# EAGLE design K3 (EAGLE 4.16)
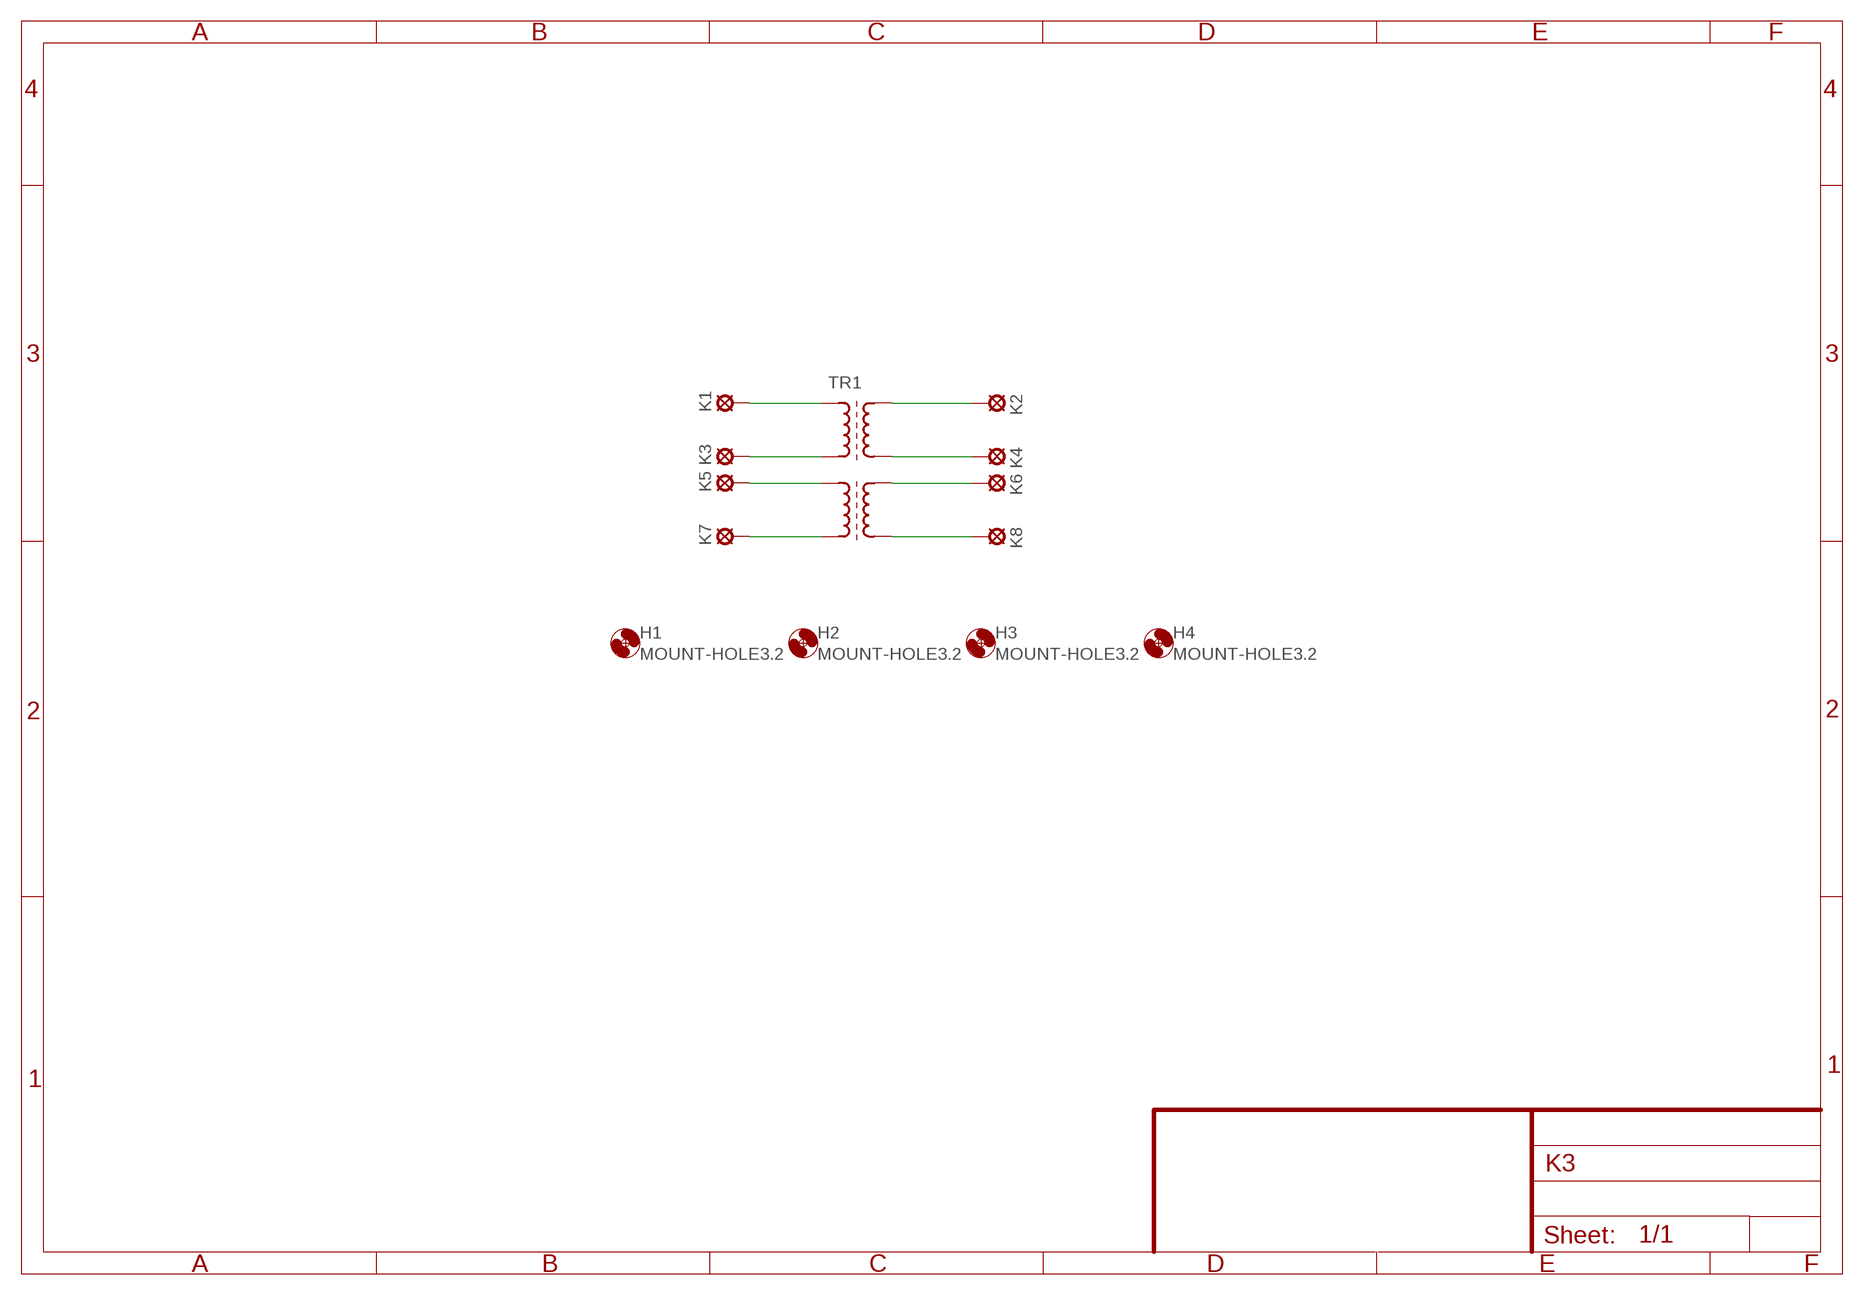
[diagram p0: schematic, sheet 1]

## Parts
H1  MOUNT-HOLE3.2  [3,2]
H2  MOUNT-HOLE3.2  [3,2]
H3  MOUNT-HOLE3.2  [3,2]
H4  MOUNT-HOLE3.2  [3,2]
K1  SE13  [SE13]
K2  SE13  [SE13]
K3  SE13  [SE13]
K4  SE13  [SE13]
K5  SE13  [SE13]
K6  SE13  [SE13]
K7  SE13  [SE13]
K8  SE13  [SE13]
TR1  RK_FRIESE4FACH  [ED26]

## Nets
N$1: K1.MP TR1.1
N$2: K3.MP TR1.2
N$3: K5.MP TR1.3
N$4: K7.MP TR1.4
N$5: K2.MP TR1.5
N$6: K4.MP TR1.6
N$7: K6.MP TR1.7
N$8: K8.MP TR1.8

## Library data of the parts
H1-H4 = holes:MOUNT-HOLE: MOUNTING HOLE with drill center marker
K1-K8 = solpad:SE13: SOLDER PAD
TR1 = FMW:RK_FRIESE4FACH

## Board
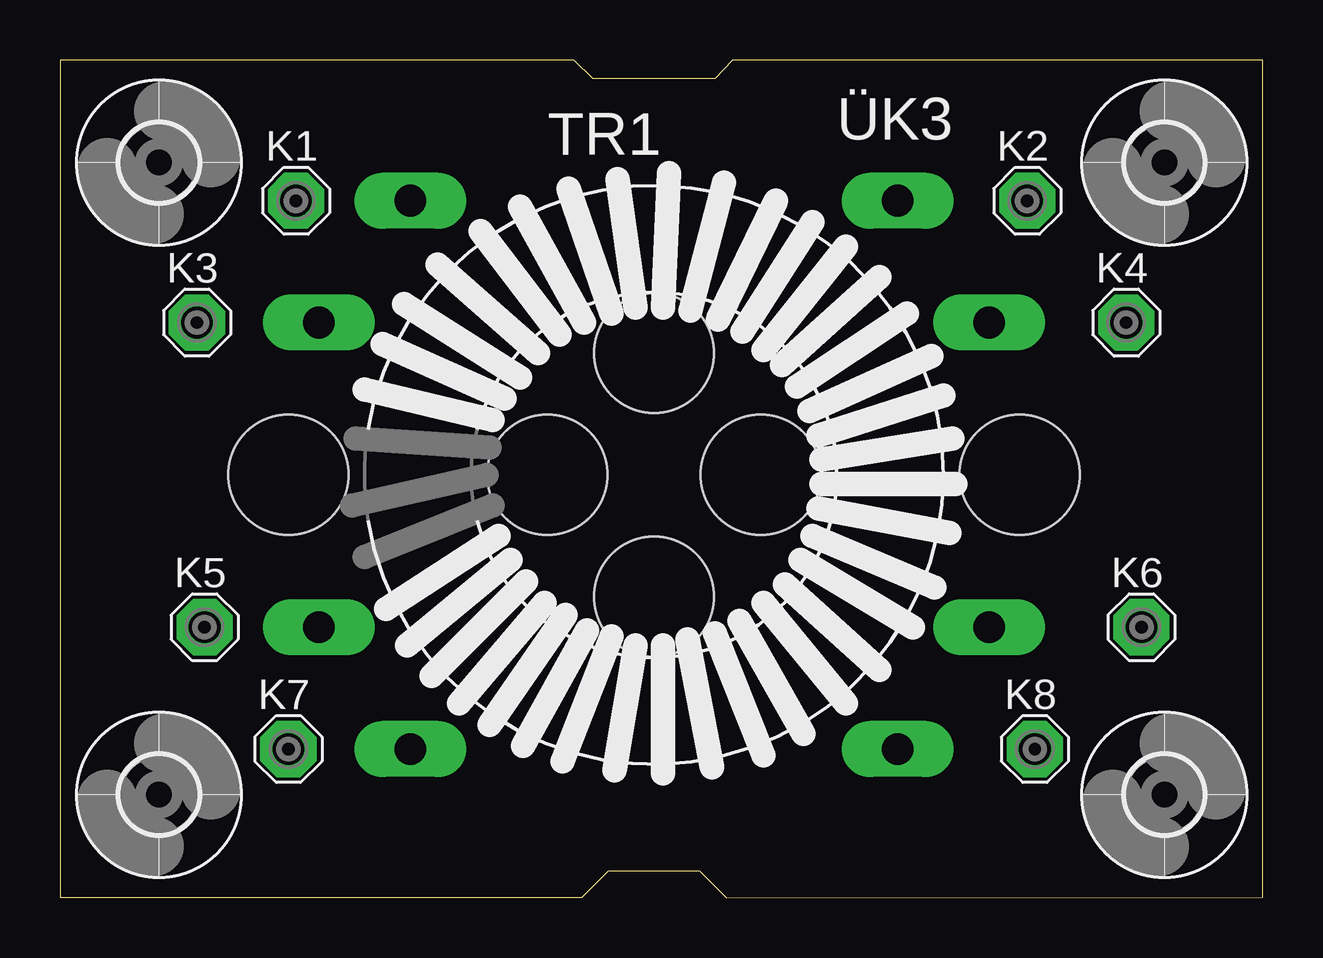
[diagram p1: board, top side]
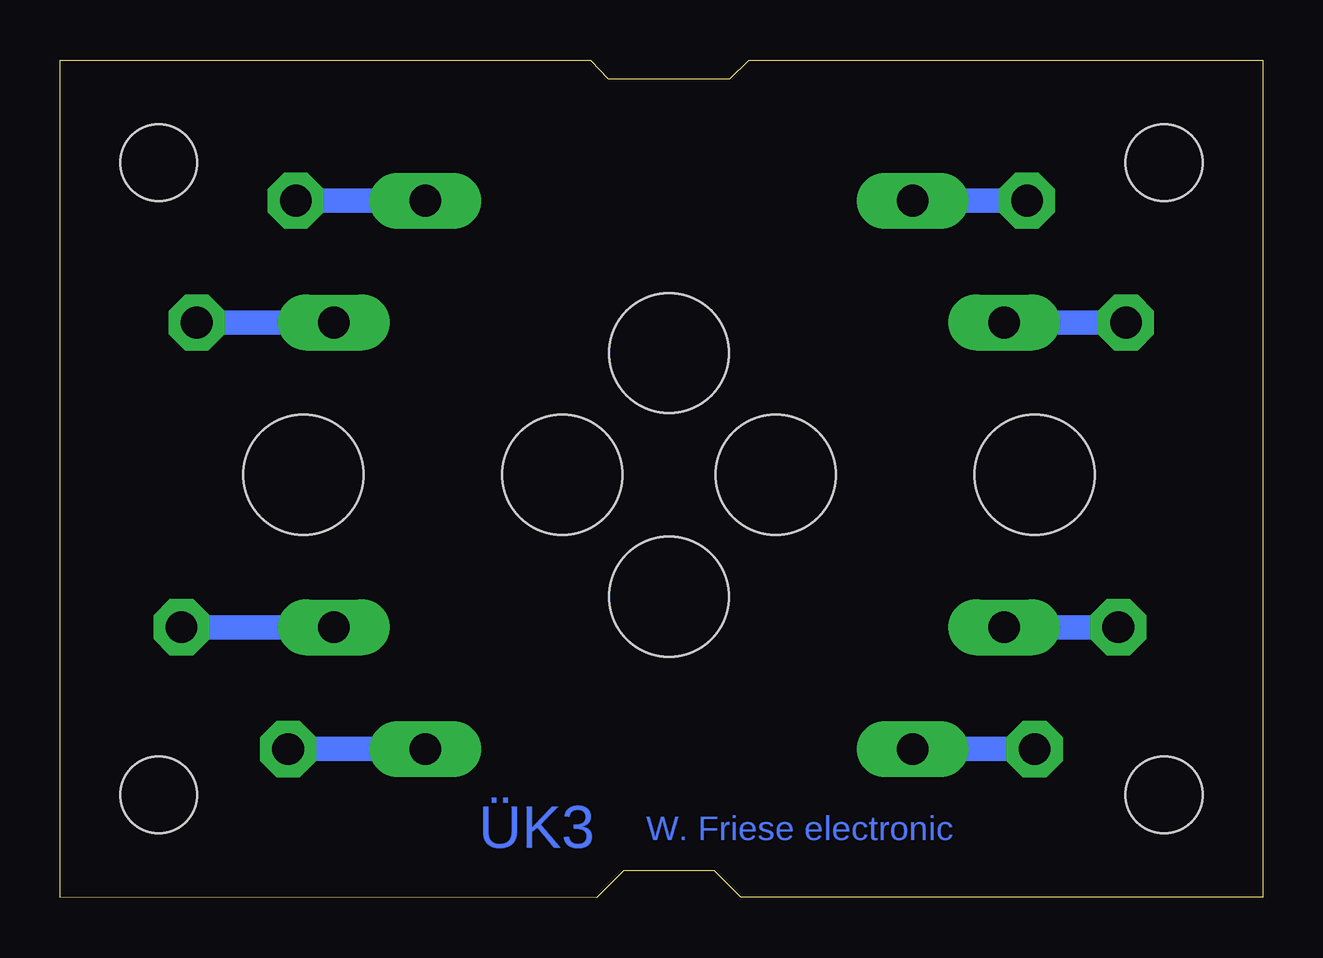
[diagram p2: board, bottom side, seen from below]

Size 50.14 x 34.93 mm. Coordinates in mm from the lower left corner, seen from the top.
Outline: 0,0.02 21.75,0.02 22.86,1.12 26.67,1.12 27.79,0 50.14,0.02 50.14,34.93 28.04,34.93 27.3,34.14 22.22,34.14 21.43,34.93 0,34.93 0,0.02
Copper layers 16: Bottom 0.035mm
Design rules "default": minimum track width 10mil, minimum drill 24mil, track to track 8mil, track to pad 8mil, pad to pad 8mil, via to via 8mil, smd to smd 8mil, copper to edge 40mil, drill to drill 8mil, minimum pad ring 10mil, minimum via ring 8mil, stop-mask expansion 0mil, vias tented up to drill 0mil, thermal gap 10mil
Holes 5 mm at 24.76,22.71 24.76,12.55 29.21,17.63 40,17.63 20.32,17.63 9.52,17.63

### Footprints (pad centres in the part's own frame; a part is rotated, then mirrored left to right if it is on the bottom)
3,2 = hole 3.2: 0,0
SE13 = drill 1.321 pad 2.159 octagon: MP 0,0
ED26 = drill 1.321 long: 1 -10.16,10.795; 2 -13.97,5.715; 3 -13.97,-6.985; 4 -10.16,-12.065; 5 10.16,10.795; 6 13.97,5.715; 7 13.97,-6.985; 8 10.16,-12.065

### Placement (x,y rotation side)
H1  46.03,4.29 0 top
H2  46.03,30.65 0 top
H3  4.12,4.29 0 top
H4  4.12,30.65 0 top
K1  9.84,29.06 0 top
K2  40.32,29.06 0 top
K3  5.71,23.98 0 top
K4  44.45,23.98 0 top
K5  6.03,11.28 0 top
K6  45.08,11.28 0 top
K7  9.52,6.2 0 top
K8  40.63,6.2 0 top
TR1  24.76,18.27 0 top

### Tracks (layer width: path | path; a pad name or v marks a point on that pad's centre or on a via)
N$1
  Bottom 1.016: TR1.1 K1.MP
N$2
  Bottom 1.016: K3.MP TR1.2
N$3
  Bottom 1.016: K5.MP TR1.3
N$4
  Bottom 1.016: K7.MP TR1.4
N$5
  Bottom 1.016: 40.63,29.06 K2.MP TR1.5
N$6
  Bottom 1.016: TR1.6 K4.MP
N$7
  Bottom 1.016: TR1.7 K6.MP
N$8
  Bottom 1.016: TR1.8 K8.MP

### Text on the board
Bottom: W. Friese electronic | ÜK3
tPlace: ÜK3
